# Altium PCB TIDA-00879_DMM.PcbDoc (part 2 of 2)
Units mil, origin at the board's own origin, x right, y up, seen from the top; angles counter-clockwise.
Board outline 2700 x 5000 mil, 4 copper layers (Layer 1 - Top Layer, Layer 2 - GND, Layer 3 - PWR, Layer 4 - Bottom Layer), stack 61.434 mil thick; 140 components, 132 nets, 483 pads, 130 vias.
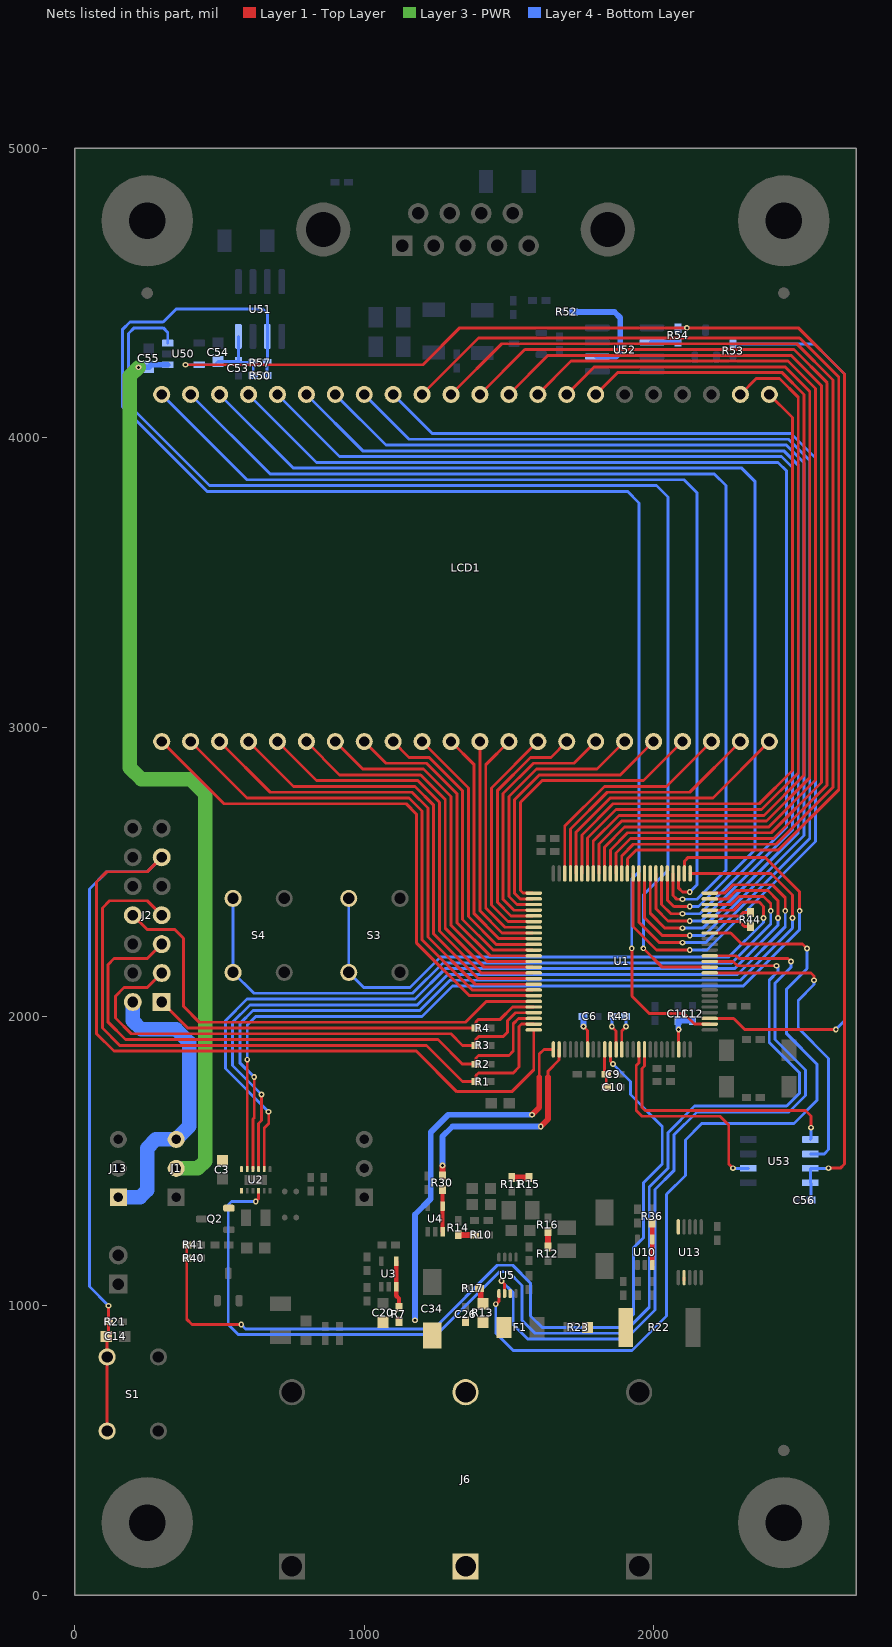
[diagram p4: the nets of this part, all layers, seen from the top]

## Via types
v1: diameter 20, hole 10, Layer 1 - Top Layer to Layer 4 - Bottom Layer, tented both sides, 127 vias
v2: diameter 19.68, hole 7.87, Layer 1 - Top Layer to Layer 4 - Bottom Layer, 3 vias

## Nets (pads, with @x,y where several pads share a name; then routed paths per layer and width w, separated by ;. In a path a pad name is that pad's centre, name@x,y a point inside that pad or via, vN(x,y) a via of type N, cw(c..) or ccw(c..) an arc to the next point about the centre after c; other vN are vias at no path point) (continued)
NetR7_2: R7.2 U3.3 U3.4 | length 164.6
  Layer 1 - Top Layer w15: U3.4@1110.59,1154.29 U3.3@1110.59,1065.71 1110.59,1034.41 1120,1025 R7.2@1120,993.62
NetR10_1: R10.1 R14.2 | length 56.9
  Layer 1 - Top Layer w20: R14.2@1325,1246.38 1326.38,1245 R10.1@1381.38,1245
NetR11_1: R11.1 R15.2 | length 60
  Layer 1 - Top Layer w20: R11.1@1510,1443.62 R15.2@1570,1443.62
NetR12_1: R12.1 R16.2 | length 52.8
  Layer 1 - Top Layer w20: R12.1@1635,1203.62 R16.2@1635,1256.38
NetR13_1: R13.1 R17.2 | length 58.2
  Layer 1 - Top Layer w20: R17.2@1398.62,1060 1403,1055.62 1403,1013.5 R13.1@1410,1006.5
NetR22_2: R22.2 R23.1 U13.5 U13.7 | length 10
  Layer 1 - Top Layer w10: U13.7@2105.32,1087.4 U13.7@2105.32,1097.4
NetR30_2: R30.2 U4.3 U4.4 | length 145.9
  Layer 1 - Top Layer w15: R30.2@1270,1401.38 1270.59,1400.79 U4.4@1270.59,1344.29 U4.3@1270.59,1255.71
NetR36_2: R36.2 U10.3 U10.4 | length 145.9
  Layer 1 - Top Layer w15: R36.2@1995,1286.38 1995.59,1285.79 U10.4@1995.59,1229.29 U10.3@1995.59,1140.71
NetR40_2: R40.2 R41.1 U1.11 | length 3105.5
  Layer 1 - Top Layer w10: R41.1@386.38,1210 R40.2@386.38,1165 386.38,953.62 405,935 v1@570,935 ; U1.11@1850.63,1885.87 1850.63,1844.37 v1(1859.53,1835.47)
  Layer 4 - Bottom Layer w10: v1(575,935) 590,920 1240,920 1460,1140 1513,1140 1575,1078 1575,965 1615,925 1885,925 1930,970 1930,1200 1965,1235 1965,1425 2030,1490 2030,1620 1920,1730 1920,1775 v1(1859.53,1835.47)
NetR43_1: R43.1 U1.13 | length 120.2
  Layer 1 - Top Layer w10: U1.13@1890,1885.87 1890,1950 v1@1905,1965
  Layer 4 - Bottom Layer w10: R43.1@1903.62,2000 1904.53,1999.09 v1(1904.53,1965.47)
NetR43_2: R43.2 U1.12 | length 120.1
  Layer 1 - Top Layer w10: v1@1855.31,1965 1870.31,1950 U1.12@1870.31,1885.87
  Layer 4 - Bottom Layer w10: v1(1855.79,1965.47) 1855.79,1999.41 R43.2@1856.38,2000
NetR44_1: R44.1 U1.46 | length 145.5
  Layer 1 - Top Layer w10: U1.46@2194.13,2347.48 2297.48,2347.48 2308.62,2358.62 R44.1@2335,2358.62
NetR44_2: R44.2 U1.45 | length 147.7
  Layer 1 - Top Layer w10: U1.45@2194.13,2327.8 2297.2,2327.8 2313.62,2311.38 R44.2@2335,2311.38
NetR52_1: R52.1 U52.6 | length 380.4
  Layer 4 - Bottom Layer w20: R52.1@1718.62,4435 R52.1@1723.62,4435 1865,4435 1885,4415 1885,4295 1870,4280 U52.6@1805.51,4280
NetR54_2: R54.2 U52.2 | length 91.1
  Layer 4 - Bottom Layer w20: U52.2@1994.49,4330 2083.62,4330 R54.2@2085,4331.38
NetS3_3: S3.3 S3.4 U1.47 | length 2062.9
  Layer 1 - Top Layer w10: U1.47@2194.13,2367.17 2277.17,2367.17 2305,2395 2365,2395 2380,2380 v1(2380,2340)
  Layer 4 - Bottom Layer w10: S3.3@946.42,2407.95 S3.4@946.42,2152.05 998.46,2100 1158.58,2100 1263.58,2205 2260,2205 2380,2325 v1(2380,2340)
NetS4_3: S4.3 S4.4 U1.48 | length 2546.6
  Layer 1 - Top Layer w10: U1.48@2194.13,2386.85 2266.85,2386.85 2295,2415 2380,2415 2405,2390 v1(2405,2365)
  Layer 4 - Bottom Layer w10: S4.3@546.42,2407.95 S4.4@546.42,2152.05 618.46,2080 1166.86,2080 1271.86,2185 2270,2185 2405,2320 v1(2405,2365)
NetU1_38: U1.38 U2.4 | length 4187.1
  Layer 1 - Top Layer w10: v1(625,1360) 634.84,1369.84 U2.4@634.84,1397.6 ; U1.38@2194.13,2190 2275,2190 2290,2175 v1(2425,2175)
  Layer 4 - Bottom Layer w10: v1(625,1360) 541.44,1360 530,1348.56 530,935 565,900 1250,900 1467.5,1117.5 1497.5,1117.5 1545,1070 1545,950 1590,905 1895,905 1985,995 1985,1410 2050,1475 2050,1598.28 2141.72,1690 2460,1690 2505,1735 2505,1805 2400,1910 2400,2125 2430,2155 2430,2170 v1(2425,2175)
NetU1_49: U1.49 U2.8 | length 2975.5
  Layer 1 - Top Layer w10: U2.8@654.53,1472.4 654.53,1614.53 670,1630 v1@670,1670.47 ; U1.49@2194.13,2406.54 2256.54,2406.54 2285,2435 2395,2435 2430,2400 v1(2430,2340)
  Layer 4 - Bottom Layer w10: v1@670,1670 v1(669.53,1670.47) 520,1820 520,1985 595,2060 1175.15,2060 1280.15,2165 2280,2165 2430,2315 v1(2430,2340)
NetU1_50: U1.50 U2.9 | length 2991.3
  Layer 1 - Top Layer w10: U2.9@634.84,1472.4 634.84,1629.84 645,1640 v1@645,1730 ; U1.50@2194.13,2426.22 2246.22,2426.22 2275,2455 2410,2455 2455,2410 v1(2455,2365)
  Layer 4 - Bottom Layer w10: v1@645,1730 v1(644.53,1730.47) 545,1830 545,1980 605,2040 1183.43,2040 1288.43,2145 2290,2145 2455,2310 v1(2455,2365)
NetU1_51: U1.51 U2.10 | length 3072
  Layer 1 - Top Layer w10: U2.10@615.16,1472.4 615.16,1645.16 620,1650 v1@620,1790.47 ; U1.51@2126.22,2494.13 2405.87,2494.13 2480,2420 v1(2480,2340)
  Layer 4 - Bottom Layer w10: v1@620,1790 v1(619.53,1790.47) 570,1840 570,1975 615,2020 1191.72,2020 1296.72,2125 2300,2125 2480,2305 v1(2480,2340)
NetU1_52: U1.52 U2.11 | length 3170.2
  Layer 1 - Top Layer w10: U2.11@595.47,1472.4 v1(595.47,1850.47) ; U1.52@2106.54,2494.13 2106.54,2536.54 2120,2550 2385,2550 2505,2430 v1(2505,2365)
  Layer 4 - Bottom Layer w10: v1(595.47,1850.47) 595.47,1970.47 625,2000 1200,2000 1305,2105 2310,2105 2505,2300 v1(2505,2365)
RESET: C14.1 J2.11 R21.1 S1.1 S1.2 U1.100 | length 4748.4
  Layer 1 - Top Layer w10: S1.2@111.42,567.04 S1.1@111.42,822.95 111.42,891.72 C14.1@108.96,894.19 116.38,901.61 R21.1@116.38,945 v1(116.38,1000) ; J2.11@300,2550 250,2500 110,2500 75,2465 75,1940 135,1880 1180,1880 1320,1740 1510,1740 1585.87,1815.87 U1.100@1585.87,1953.78
  Layer 4 - Bottom Layer w10: v1(116.38,1000) 50,1066.38 50,2440 110,2500 250,2500 J2.11@300,2550
RXD: R50.2 R57.1 U1.27 U51.6 | length 4965.7
  Layer 1 - Top Layer w10: v1@1925,2235 1925,2070 1985,2010 2105,2010 2141.54,1973.46 U1.27@2194.13,1973.46
  Layer 4 - Bottom Layer w10: R50.2@663.62,4215 R57.1@663.62,4260 665,4261.38 U51.6@665,4350.51 665,4430 650,4445 350,4445 305,4400 190,4400 165,4375 165,4106.72 456.72,3815 1910,3815 1950,3775 1950,2500 1924.53,2474.53 v1(1924.53,2235.47)
S0: LCD1.1 U1.94 | length 1905.3
  Layer 1 - Top Layer w10: LCD1.1@300,2950 515,2735 1145,2735 1180,2700 1180,2255 1363.11,2071.89 U1.94@1580.87,2071.89
S1: LCD1.2 U1.93 | length 1797.1
  Layer 1 - Top Layer w10: LCD1.2@400,2950 595,2755 1155,2755 1200,2710 1200,2265 1373.43,2091.57 U1.93@1580.87,2091.57
S2: LCD1.3 U1.92 | length 1689
  Layer 1 - Top Layer w10: LCD1.3@500,2950 675,2775 1165,2775 1220,2720 1220,2275 1383.74,2111.26 U1.92@1580.87,2111.26
S3: LCD1.4 U1.91 | length 1580.8
  Layer 1 - Top Layer w10: LCD1.4@600,2950 755,2795 1175,2795 1240,2730 1240,2285 1394.06,2130.94 U1.91@1580.87,2130.94
S4: LCD1.5 U1.90 | length 1472.7
  Layer 1 - Top Layer w10: LCD1.5@700,2950 835,2815 1185,2815 1260,2740 1260,2295 1404.37,2150.63 U1.90@1580.87,2150.63
S5: LCD1.6 U1.89 | length 1364.5
  Layer 1 - Top Layer w10: LCD1.6@800,2950 915,2835 1195,2835 1280,2750 1280,2305 1414.69,2170.31 U1.89@1580.87,2170.31
S6: LCD1.7 U1.88 | length 1256.3
  Layer 1 - Top Layer w10: LCD1.7@900,2950 995,2855 1205,2855 1300,2760 1300,2315 1425,2190 U1.88@1580.87,2190
S7: LCD1.8 U1.87 | length 1148.2
  Layer 1 - Top Layer w10: LCD1.8@1000,2950 1075,2875 1215,2875 1320,2770 1320,2325 1435.32,2209.68 U1.87@1580.87,2209.68
S8: LCD1.9 U1.86 | length 1040
  Layer 1 - Top Layer w10: LCD1.9@1100,2950 1155,2895 1225,2895 1340,2780 1340,2335 1445.63,2229.37 U1.86@1580.87,2229.37
S9: LCD1.10 U1.85 | length 931.9
  Layer 1 - Top Layer w10: LCD1.10@1200,2950 1360,2790 1360,2345 1455.94,2249.06 U1.85@1580.87,2249.06
S10: LCD1.11 U1.84 | length 864.7
  Layer 1 - Top Layer w10: LCD1.11@1300,2950 1380,2870 1380,2355 1466.26,2268.74 U1.84@1580.87,2268.74
S11: LCD1.12 U1.83 | length 797.6
  Layer 1 - Top Layer w10: LCD1.12@1400,2950 1400,2365 1476.57,2288.43 U1.83@1580.87,2288.43
S12: LCD1.13 U1.82 | length 796.7
  Layer 1 - Top Layer w10: LCD1.13@1500,2950 1420,2870 1420,2375 1486.89,2308.11 U1.82@1580.87,2308.11
S13: LCD1.14 U1.81 | length 795.8
  Layer 1 - Top Layer w10: U1.81@1580.87,2327.8 1497.2,2327.8 1440,2385 1440,2790 LCD1.14@1600,2950
S14: LCD1.15 U1.80 | length 836
  Layer 1 - Top Layer w10: U1.80@1580.87,2347.48 1507.52,2347.48 1460,2395 1460,2780 1575,2895 1645,2895 LCD1.15@1700,2950
S15: LCD1.16 U1.79 | length 876.1
  Layer 1 - Top Layer w10: U1.79@1580.87,2367.17 1517.83,2367.17 1480,2405 1480,2770 1585,2875 1725,2875 LCD1.16@1800,2950
S16: LCD1.17 U1.78 | length 916.2
  Layer 1 - Top Layer w10: U1.78@1580.87,2386.85 1528.15,2386.85 1500,2415 1500,2760 1595,2855 1805,2855 LCD1.17@1900,2950
S17: LCD1.18 U1.77 | length 956.4
  Layer 1 - Top Layer w10: U1.77@1580.87,2406.54 1538.46,2406.54 1520,2425 1520,2750 1605,2835 1885,2835 LCD1.18@2000,2950
S18: LCD1.19 U1.76 | length 996.5
  Layer 1 - Top Layer w10: U1.76@1580.87,2426.22 1548.78,2426.22 1540,2435 1540,2740 1615,2815 1965,2815 LCD1.19@2100,2950
S19: LCD1.20 U1.73 | length 791.8
  Layer 1 - Top Layer w10: U1.73@1693.15,2494.13 1693.15,2658.15 1830,2795 2045,2795 LCD1.20@2200,2950
S20: LCD1.21 U1.72 | length 866
  Layer 1 - Top Layer w10: U1.72@1712.83,2494.13 1712.83,2647.83 1840,2775 2125,2775 LCD1.21@2300,2950
S21: LCD1.22 U1.71 | length 940.3
  Layer 1 - Top Layer w10: U1.71@1732.52,2494.13 1732.52,2637.52 1850,2755 2205,2755 LCD1.22@2400,2950
S22: LCD1.23 U1.70 | length 2286.3
  Layer 1 - Top Layer w10: U1.70@1752.2,2494.13 1752.2,2627.2 1860,2735 2365,2735 2480,2850 2480,4070 LCD1.23@2400,4150
S23: LCD1.24 U1.69 | length 2492
  Layer 1 - Top Layer w10: U1.69@1771.89,2494.13 1771.89,2616.89 1870,2715 2373.28,2715 2500,2841.72 2500,4140 2435,4205 2355,4205 LCD1.24@2300,4150
S24: LCD1.29 U1.68 | length 3033.5
  Layer 1 - Top Layer w10: U1.68@1791.57,2494.13 1791.57,2606.57 1880,2695 2381.57,2695 2520,2833.43 2520,4150 2445,4225 1875,4225 LCD1.29@1800,4150
S25: LCD1.30 U1.67 | length 3175.1
  Layer 1 - Top Layer w10: LCD1.30@1700,4150 1795,4245 2455,4245 2540,4160 2540,2825.15 2389.85,2675 1890,2675 1811.26,2596.26 U1.67@1811.26,2494.13
S26: LCD1.31 U1.66 | length 3316.6
  Layer 1 - Top Layer w10: LCD1.31@1600,4150 1715,4265 2465,4265 2560,4170 2560,2816.86 2398.14,2655 1900,2655 1830.94,2585.94 U1.66@1830.94,2494.13
S27: LCD1.32 U1.65 | length 3458.2
  Layer 1 - Top Layer w10: LCD1.32@1500,4150 1635,4285 2475,4285 2580,4180 2580,2808.58 2406.42,2635 1910,2635 1850.63,2575.63 U1.65@1850.63,2494.13
S28: LCD1.33 U1.64 | length 3599.7
  Layer 1 - Top Layer w10: LCD1.33@1400,4150 1555,4305 2485,4305 2600,4190 2600,2800.29 2414.71,2615 1920,2615 1870.31,2565.31 U1.64@1870.31,2494.13
S29: LCD1.34 U1.63 | length 3741.3
  Layer 1 - Top Layer w10: LCD1.34@1300,4150 1475,4325 2495,4325 2620,4200 2620,2792.01 2422.99,2595 1930,2595 1890,2555 U1.63@1890,2494.13
S30: LCD1.35 U1.62 | length 3882.8
  Layer 1 - Top Layer w10: LCD1.35@1200,4150 1395,4345 2505,4345 2640,4210 2640,2783.73 2431.27,2575 1940,2575 1909.68,2544.68 U1.62@1909.68,2494.13
S31: LCD1.36 U1.61 | length 3879
  Layer 1 - Top Layer w10: U1.61@1929.37,2494.13 1929.37,2310.63 2010,2230 v1(2125,2230)
  Layer 4 - Bottom Layer w10: LCD1.36@1100,4150 1235,4015 2475,4015 2560,3930 2560,2605 2185,2230 v1(2125,2230)
S32: LCD1.37 U1.60 | length 3878.9
  Layer 1 - Top Layer w10: U1.60@1949.06,2494.13 1949.06,2325.94 2020,2255 v1(2100,2255)
  Layer 4 - Bottom Layer w10: LCD1.37@1000,4150 1155,3995 2466.72,3995 2540,3921.72 2540,2615 2180,2255 v1(2100,2255)
S33: LCD1.38 U1.59 | length 3878.8
  Layer 1 - Top Layer w10: U1.59@1968.74,2494.13 1968.74,2341.26 2030,2280 v1(2125,2280)
  Layer 4 - Bottom Layer w10: LCD1.38@900,4150 1075,3975 2458.43,3975 2520,3913.43 2520,2625 2175,2280 v1(2125,2280)
S34: LCD1.39 U1.58 | length 3878.8
  Layer 1 - Top Layer w10: U1.58@1988.43,2494.13 1988.43,2356.57 2040,2305 v1(2100,2305)
  Layer 4 - Bottom Layer w10: LCD1.39@800,4150 995,3955 2450.15,3955 2500,3905.15 2500,2635 2170,2305 v1(2100,2305)
S35: LCD1.40 U1.57 | length 3878.7
  Layer 1 - Top Layer w10: U1.57@2008.11,2494.13 2008.11,2371.89 2050,2330 v1(2125,2330)
  Layer 4 - Bottom Layer w10: LCD1.40@700,4150 915,3935 2441.86,3935 2480,3896.86 2480,2645 2165,2330 v1(2125,2330)
S36: LCD1.41 U1.56 | length 3876.5
  Layer 1 - Top Layer w10: U1.56@2027.8,2494.13 2027.8,2387.2 2060,2355 v1(2100,2355)
  Layer 4 - Bottom Layer w10: LCD1.41@600,4150 835,3915 2430,3915 2460,3885 2460,2655 2160,2355 v1(2100,2355)
S37: LCD1.42 U1.55 | length 3733.5
  Layer 1 - Top Layer w10: U1.55@2047.48,2494.13 2047.48,2402.52 2070,2380 v1(2125,2380)
  Layer 4 - Bottom Layer w10: LCD1.42@500,4150 755,3895 2305,3895 2350,3850 2350,2575 2155,2380 v1(2125,2380)
S38: LCD1.43 U1.54 | length 3616.3
  Layer 1 - Top Layer w10: U1.54@2067.17,2494.13 2067.17,2417.83 2080,2405 v1(2100,2405)
  Layer 4 - Bottom Layer w10: LCD1.43@400,4150 675,3875 2210,3875 2250,3835 2250,2505 2150,2405 v1(2100,2405)
S39: LCD1.44 U1.53 | length 3475.8
  Layer 1 - Top Layer w10: U1.53@2086.85,2494.13 2086.85,2443.15 2100,2430 v1(2125,2430)
  Layer 4 - Bottom Layer w10: LCD1.44@300,4150 595,3855 2105,3855 2150,3810 2150,2455 v1(2125,2430)
SCLK: U1.36 U53.6 | length 1100.5
  Layer 1 - Top Layer w10: U1.36@2194.13,2150.63 2544.37,2150.63 2555,2140 v1(2555,2125)
  Layer 4 - Bottom Layer w10: U53.6@2542.28,1525 2590,1525 2605,1540 2605,1855 2500,1960 2500,2055 2555,2110 v1(2555,2125)
SIMO: U1.17 U53.5 | length 882.6
  Layer 1 - Top Layer w10: U1.17@1968.74,1885.87 1968.74,1828.74 1960,1820 1960,1685 1970,1675 2525,1675 2544.53,1655.47 v1(2544.53,1615.47)
  Layer 4 - Bottom Layer w10: U53.5@2542.28,1575 2544.53,1577.24 v1(2544.53,1615.47)
SOMI: U1.16 U53.2 | length 764.9
  Layer 1 - Top Layer w10: U1.16@1949.06,1885.87 1949.06,1839.06 1940,1830 1940,1675 1960,1655 2230,1655 2260,1625 2260,1490 v1(2274.53,1475.47) v1@2275,1475
  Layer 4 - Bottom Layer w10: v1(2274.53,1475.47) 2275,1475 U53.2@2327.72,1475
TCK: J2.7 R1.1 U1.99 | length 2395.3
  Layer 1 - Top Layer w10: J2.7@300,2350 250,2400 120,2400 95,2375 95,1960 155,1900 1215,1900 1340,1775 R1.1@1386.38,1775 1386.38,1796.38 1395,1805 1515,1805 1535,1825 1535,1965 1543.46,1973.46 U1.99@1585.87,1973.46
TDI: J2.3 R3.1 U1.97 | length 1836
  Layer 1 - Top Layer w10: J2.3@300,2150 250,2100 170,2100 140,2070 140,1995 195,1940 1300,1940 1340,1900 R3.1@1386.38,1900 1386.38,1921.38 1395,1930 1480,1930 1495,1945 1495,1985 1522.83,2012.83 U1.97@1585.87,2012.83
TDO: J2.1 R4.1 U1.96 | length 1365.7
  Layer 1 - Top Layer w10: J2.1@300,2050 390,1960 R4.1@1386.38,1960 1386.38,1981.38 1395,1990 1470,1990 1512.52,2032.52 U1.96@1585.87,2032.52
TEST/SBWTCK: J2.8 U1.95 | length 1706.7
  Layer 1 - Top Layer w10: J2.8@200,2350 250,2300 345,2300 375,2270 375,2035 430,1980 1350,1980 1422.2,2052.2 U1.95@1585.87,2052.2
TEST_EN: U1.37 U50.3 | length 4280.9
  Layer 1 - Top Layer w10: v1@1965,2235 2029.69,2170.31 U1.37@2194.13,2170.31
  Layer 4 - Bottom Layer w10: U50.3@320.87,4327.4 320.87,4364.13 305,4380 205,4380 185,4360 185,4115 465,3835 2010,3835 2050,3795 2050,2505 1964.53,2419.53 v1(1964.53,2235.47)
TMS: J2.5 R2.1 U1.98 | length 2078.6
  Layer 1 - Top Layer w10: J2.5@300,2250 250,2200 135,2200 115,2180 115,1980 175,1920 1255,1920 1340,1835 R2.1@1386.38,1835 1386.38,1856.38 1395,1865 1500,1865 1515,1880 1515,1975 1533.15,1993.15 U1.98@1585.87,1993.15
TXD: R53.1 U1.28 | length 3157
  Layer 1 - Top Layer w10: U1.28@2194.13,1993.15 2276.85,1993.15 2315,1955 v1(2630,1955)
  Layer 4 - Bottom Layer w10: R53.1@2275,4323.62 2556.38,4323.62 2660,4220 2660,1985 v1(2630,1955)
V+: C20.1 C26.2 C34.2 F1.1 J6.1 J6.2 R7.1 R13.2 U1.1 U5.7 | length 1323.3
  Layer 1 - Top Layer w10: 1605,1790 1605,1870 1620.87,1885.87 U1.1@1653.78,1885.87
  Layer 1 - Top Layer w20: v1(1580,1660) 1605,1685 1605,1790
  Layer 4 - Bottom Layer w20: v1(1175,950) 1175,1315 1230,1370 1230,1600 1290,1660 v1(1580,1660)
V-: R30.1 U1.2 | length 783
  Layer 1 - Top Layer w10: 1635,1790 1635,1810.56 1673.46,1849.02 U1.2@1673.46,1885.87
  Layer 1 - Top Layer w20: R30.1@1270,1448.62 v1(1270,1485) ; v1(1610,1620) 1635,1645 1635,1790
  Layer 4 - Bottom Layer w20: v1(1270,1485) 1270,1585 1305,1620 v1(1610,1620)
VASYS: C9.1 C10.2 U1.10 | length 133.1
  Layer 1 - Top Layer w10: U1.10@1830.94,1885.87 1830.94,1805.43 C9.1@1836.38,1800 C10.2@1836.38,1755
VCORE: C11.1 C12.1 U1.23 | length 151.3
  Layer 1 - Top Layer w10: U1.23@2086.85,1885.87 v1(2086.85,1955)
  Layer 4 - Bottom Layer w20: v1(2086.85,1955) 2085,1956.85 C11.1@2085,1986.38 C12.1@2135,1986.38
VIN: C3.1 C55.1 J1.2 Q2.2 U2.1 U2.12 U50.1 | length 3178.2
  Layer 3 - PWR w50: v1(220,4243.5) 190,4213.5 190,2860 230,2820 400,2820 450,2770 450,1500 425,1475 J1.2@350,1475
  Layer 4 - Bottom Layer w20: v1(220,4243.5) C55.1@255,4243.5 264.09,4252.6 U50.1@320.87,4252.6
VJTAG: J1.3 J2.2 J13.1 | length 1012.5
  Layer 4 - Bottom Layer w50: J13.1@150,1375 225.01,1375 250,1400 250,1545 280.01,1575 J1.3@350,1575 395,1620 395,1910 350,1955 230,1955 200,1985 J2.2@200,2050
VRANGE_0: U1.39 U5.6 | length 2728.7
  Layer 1 - Top Layer w10: v1@1475,1085 1485.16,1074.84 U5.6@1485.16,1042.01 ; U1.39@2194.13,2209.68 2285.32,2209.68 2295,2200 2465,2200 v1(2475,2190)
  Layer 4 - Bottom Layer w10: v1(1474.53,1085.47) 1515,1045 1515,935 1565,885 1905,885 2005,985 2005,1401.72 2070,1466.72 2070,1590 2150,1670 2468.28,1670 2525,1726.72 2525,1815 2420,1920 2420,2115 2475,2170 v1(2475,2190)
VRANGE_1: U1.43 U5.5 | length 2908.9
  Layer 1 - Top Layer w10: v1@1455,1005 1465.47,1015.47 U5.5@1465.47,1042.01 ; U1.43@2194.13,2288.43 2266.57,2288.43 2305,2250 2515,2250 v1(2530,2235)
  Layer 4 - Bottom Layer w10: v1(1454.53,1005.47) 1454.53,905.47 1515,845 1925,845 2045,965 2045,1385.15 2110,1450.15 2110,1573.43 2166.57,1630 2484.85,1630 2565,1710.15 2565,1835 2460,1940 2460,2095 2530,2165 v1(2530,2235)
VREF: C6.1 U1.7 | length 119.9
  Layer 1 - Top Layer w10: v1@1758.46,1965 1771.89,1951.57 U1.7@1771.89,1885.87
  Layer 4 - Bottom Layer w20: C6.1@1756.38,2000 1757.99,1998.39 v1(1757.99,1965.47)
VTEST: C53.1 C54.1 C56.1 R50.1 R54.1 R57.2 U50.5 U51.8 U53.7 U53.8 | length 5763.5
  Layer 1 - Top Layer w10: v1(382.6,4252.6) 1202.6,4252.6 1330,4380 v1(2115,4380) 2500,4380 2660,4220 2660,1490 2645.47,1475.47 v1(2604.53,1475.47)
  Layer 4 - Bottom Layer w10: v1(382.6,4252.6) U50.5@429.13,4252.6 484.09,4252.6 C54.1@495,4263.5 495.12,4263.62 C53.1@565,4263.62 ; U51.8@565,4350.51 C53.1@565,4263.62 ; R50.1@616.38,4215 R57.2@616.38,4260 568.62,4260 C53.1@565,4263.62 ; R54.1@2085,4378.62 2086.38,4380 v1(2115,4380) ; C56.1@2543.62,1365 2543.62,1423.66 U53.8@2542.28,1425 U53.7@2542.28,1475 v1@2605,1475
pads on no net: FID1.1 FID2.1 FID3.1 FID4.1 FID5.1 FID6.1 H3.1 H4.1 H8.1 H9.1 J2.6 J2.10 J2.12 J2.13 J2.14 J11.1 J11.6 J11.8 J11.9 U1.15 U1.30 U1.31 U1.40 U1.41 U2.7 U13.10 U51.1 U51.4 U51.7 U52.1 U52.4 U52.7 U53.3
copper on no net: | length 35.2
  Layer 1 - Top Layer w20: 1362.24,1117.6 v1(1397.4,1117.6)

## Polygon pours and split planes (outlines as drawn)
DGND on Layer 2 - GND "Layer 2 - GND - DGND" (solid, remove dead copper, pour order 8): 20,20 2680,20 2680,4980 20,4980
AGND on Layer 2 - GND "Layer 2 - GND - AGND" (solid, remove dead copper, pour order 6): 840,900 840,1400 770,1400 770,1650 1520,1650 1520,2010 1950,2010 1950,1370 2340,1370 2340,900
DGND on Layer 3 - PWR "Layer 3 - PWR - DGND" (solid, remove dead copper, pour order 7): 20,20 2680,20 2680,4980 20,4980
AGND on Layer 3 - PWR "Layer 3 - PWR - AGND" (solid, remove dead copper, pour order 5): 840,900 840,1400 770,1400 770,1650 1520,1650 1520,2010 1950,2010 1950,1370 2340,1370 2340,900

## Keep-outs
Keep-Out Layer:
  text ".Layer_Name" at 577,-858.49 h60

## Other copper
Layer 1 - Top Layer:
  rectangle net NetC27_1: 674,845 822,900
  region net AGND: 1758,1915 1758,1818 1753,1813 1753,1735 1743,1725 1729,1725 1719,1735 1719,1814 1726,1821 1726,1915
  region net DVCC: 1818,1915 1818,1831 1800,1813 1800,1735 1790,1725 1775,1725 1765,1735 1765,1810 1805,1850 1805,1915
  region net DVCC: 2041,1915 2041,1735 2051,1725 2085,1725 2095,1735 2095,1822 2080,1837 2066,1837 2054,1849 2054,1915
  region net DGND: 1660,2465 1620,2465 1585,2500 1585,2675 1595,2685 1618,2685 1628,2675 1628,2552 1660,2520
  region net DVSYS: 1680,2465 1680,2675 1670,2685 1650,2685 1640,2675 1640,2560 1667,2533 1667,2465
  region net DGND: 490,1420 490,1460 495,1465 535,1465 547,1453 685,1453 685,1417 493,1417
  region net VIN: 390,1515 415,1540 563,1540 581,1522 581,1462 561,1462 543,1480 485,1480 470,1465 470,1415 485,1400 553,1400 561,1408 581,1408 581,1356 550,1325 470,1325 410,1385 410,1415 390,1435 325,1435 310,1450 310,1500 325,1515
  region net DGND: 1982,1915 2014,1915 2014,1846 2030,1830 2030,1735 2020,1725 1990,1725 1980,1735 1980,1820 1982,1822
  region net DGND: 2350,1705 2485,1705 2500,1720 2500,1920 2485,1935 2350,1935
  region net NetC27_1: 880,45 945,110 945,900 690,900 690,45
  region net V+: 1105,45 1040,110 1040,965 1450,965 1499,1014 1499,1058 1511,1058 1511,111 1445,45
  region net NetJ9_1: 2100,45 2165,110 2165,1037 2151,1051 2151,1300 2138,1300 2138,1051 2100,1013 2100,935 1895,730 1895,45
  region net I+: 1565,880 1720,880 1730,890 1730,960 1720,970 1565,970
  region net NetR22_2: 1750,975 1770,995 2005,995 2030,1020 2063.5,1053.5 2088.5,1053.5 2099,1064 2099,1170 2079.5,1189.5 2079.5,1300 2092,1300 2092,1195 2112,1175 2112,1061 2112,1047 2085,1020 2085,945 1995,855 1770,855 1750,875
  region net NetC27_1: 674,845 674,838 692,820 703,831 708,831 708,851 700,859 686,845
  text ".Layer_Name" at 577,-858.49 h60
Layer 2 - GND:
  pour cut-out: 1510,1680 1440,1680 1440,2040 1510,2040
  pour cut-out: 150,2000 150,2700 350,2700 350,2490 260,2490 260,2410 350,2410 350,2000
  pour cut-out: 1095,1040 1125,1040 1125,1180 1095,1180
  pour cut-out: 1255,1230 1285,1230 1285,1370 1255,1370
  pour cut-out: 1979.99,1114.41 2009.99,1114.41 2009.99,1254.41 1979.99,1254.41
Layer 3 - PWR:
  pour cut-out: 1095,1040 1125,1040 1125,1180 1095,1180
  pour cut-out: 1255,1230 1285,1230 1285,1370 1255,1370
  pour cut-out: 1979.99,1114.41 2009.99,1114.41 2009.99,1254.41 1979.99,1254.41
  pour cut-out: 150,2000 150,2700 350,2700 350,2490 260,2490 260,2410 350,2410 350,2000
Layer 4 - Bottom Layer:
  text ".Layer_Name" at 577,-858.49 h60

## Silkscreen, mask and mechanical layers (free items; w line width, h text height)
Top Overlay:
  lines w7: 420,1640 420,1535 670,1535 670,1640 ; 558.07,840 2410,840 2410,1640 ; 642,837 643,838 643,1066 713,1066 919,1066 920,1067 920,1640 ; 642,980 616.13,980 558.07,980 60,980 60,1640 920,1640 ; 1345,1640 1345,2655 2595,2655 2595,1640 2410,1640 ; 1845,1640 1845,1535 2095,1535 2095,1640 ; 1845,2655 1845,2550 2095,2550 2095,2655 ; 920,1640 2410,1640
  text "MCU" at 1875,2570 h100
  text "Range" at 495,2029 h60
  text "Mode" at 929,2019 h60
  text "3" at 1074,1564 h40
  text "3" at 230,1560 h40
  text "PWR" at 445,1555 h100
  text "AFE" at 1880,1555 h100
  text "2" at 1072,1457 h40
  text "2" at 228,1453 h40
  text "1" at 1081,1348 h40
  text "1" at 237,1344 h40
  text "+" at 220,1158 h60
  text "-" at 217,1019 h60
  text "RESET" at 65,452 h100
  text "WARNING / HIGH / VOLTAGE" at 2249,371 h75
  text ".Layer_Name" at 577,-858.49 h60
Bottom Overlay:
  text ".Layer_Name" at 577,-858.49 h60
Top Paste:
  text ".Layer_Name" at 577,-858.49 h60
Bottom Paste:
  text ".Layer_Name" at 577,-858.49 h60
Top Solder:
  text ".Layer_Name" at 577,-858.49 h60
  text ".Layer_Name" at 577,-858.49 h60
Bottom Solder:
  text ".Layer_Name" at 577,-858.49 h60
Drill Guide:
  text ".Layer_Name" at 577,-858.49 h60
M1 Board Outline:
  the board outline again, w10
  text ".Layer_Name" at 577,-858.49 h60
M2 Board Dimensions:
  rectangle: 0,-275 125,-150
  rectangle: 125,-400 500,-275
  lines w7: 0,-275 1000,-275 ; 125,-400 125,-150 ; 250,-400 250,-150 ; 500,-400 500,-150 ; 750,-400 750,-150 ; 0,-400 1000,-400 1000,-150 0,-150 0,-400
  text ".Layer_Name" at 577,-858.49 h60
M3 3D STEP Top:
  text ".Layer_Name" at 577,-858.49 h60
M4 3D STEP Bottom:
  text ".Layer_Name" at 577,-858.49 h60
M5 Assembly Top:
  lines w10: -292,-930.17 6308,-930.17 ; -292,-726.83 6310,-726.83 ; -292,-523.5 -292,-1133.5 3713,-1133.5 6310,-1133.5 6310,-523.5 -291.5,-523.5 -291.5,-1133.5 1284,-1133.5 ; 2173,-1133.5 2173,-523.5 ; 3440,-726.83 3440,-523.5 ; 4280,-726.83 4280,-523.5 ; 4902,-1140 4902,-937.17
  text "COMPONENTS MARKED 'DNP' SHOULD NOT BE POPULATED." at 1153.5,-318.5 h60
  text "ASSEMBLY VARIANT:" at 1153,-434 h60
  text ".VariantName" at 2189,-434 h60
  text "PCB VIEWED FROM TOP SIDE" at -228.5,-655.67 h60
  text "BOARD #:" at 2248,-655.67 h60
  text ".PRJ_Number" at 2793.5,-655.67 h60
  text "REV:" at 3638,-655.67 h60
  text ".PCB_Rev" at 3929.5,-655.67 h60
  text "SVN REV:" at 4476,-655.67 h60
  text ".VersionControl_RevNumber" at 4982,-655.67 h60
  text "TID #:" at 2248,-859 h60
  text ".TID" at 2793.5,-859 h60
  text "PLOT NAME =" at -228.5,-1064.34 h60
  text ".plot_File_Name" at 577,-1064.34 h60
  text "GENERATED    :" at 2250,-1064.34 h60
  text ".Print_Date" at 3119.5,-1064.34 h60
  text ".Print_Time" at 3848.5,-1064.34 h60
  text "TEXAS INSTRUMENTS" at 5113,-1064.34 h60
M6 Assembly Bottom:
  lines w10: -292.5,-727.33 6309.5,-727.33 ; -290.5,-930.67 6309.5,-930.67 ; 1115.5,-1140.5 1115.5,-937.67 ; 1737.5,-727.33 1737.5,-524 ; 2577.5,-727.33 2577.5,-524 ; 3844.5,-1134 3844.5,-524 ; 4733.5,-1134 6309,-1134 6309,-524 -292.5,-524 -292.5,-1134 2304.5,-1134 6309.5,-1134 6309.5,-524
  text "COMPONENTS MARKED 'DNP' SHOULD NOT BE POPULATED." at 6102,-318 h60
  text ".VariantName" at 5058,-434 h60
  text "ASSEMBLY VARIANT:" at 6097,-434 h60
  text ".VersionControl_RevNumber" at 1035.5,-656.17 h60
  text "SVN REV:" at 1541.5,-656.17 h60
  text ".PCB_Rev" at 2088,-656.17 h60
  text "REV:" at 2379.5,-656.17 h60
  text ".PRJ_Number" at 3224,-656.17 h60
  text "BOARD #:" at 3769.5,-656.17 h60
  text "PCB VIEWED FROM BOTTOM SIDE" at 6246,-656.17 h60
  text ".TID" at 3224,-859.5 h60
  text "TID #:" at 3769.5,-859.5 h60
  text "TEXAS INSTRUMENTS" at 904.5,-1064.84 h60
  text ".Print_Time" at 2169,-1064.84 h60
  text ".Print_Date" at 2898,-1064.84 h60
  text "GENERATED    :" at 3767.5,-1064.84 h60
  text ".plot_File_Name" at 5440.5,-1064.84 h60
  text "PLOT NAME =" at 6246,-1064.84 h60
M9 Title Sheet:
  drawing of 1178 lines, arcs and shapes, not listed
  text "1" at 739.84,8036.5 h70
  text "2" at 3235.5,8036.5 h70
  text "3" at 5724.84,8036.5 h70
  text "4" at 8231.51,8036.5 h70
  text "5" at 10730.5,8036.5 h70
  text "6" at 13235.5,8036.5 h70
  text "A" at -416.5,6893.5 h70
  text "A" at 14383.5,6893.5 h70
  text "B" at -416.5,4513.5 h70
  text "B" at 14383.5,4513.5 h70
  text "C" at -416.5,2138.5 h70
  text "C" at 14383.5,2138.5 h70
  text "PROJECT TITLE:" at 11343.5,277.5 h45
  text ".PRJ_Title" at 11393.5,144.17 h70
  text "DESIGNED FOR:" at 11343.5,-23.5 h45
  text ".PRJ_Customer" at 11393.5,-163.5 h70
  text "D" at -416.5,-231.5 h70
  text "D" at 14383.5,-231.5 h70
  text "FILE NAME:" at 11343.5,-323.5 h45
  text ".PCB_File_Name_No_Path" at 11393.5,-443.5 h70
  text "Texas Instruments (TI) and/or its licensors do not warrant the accuracy or completeness of this specification" at 6374,-605.34 h45
  text "ENGINEER:" at 11343.5,-613.5 h45
  text "LAYOUT BY:" at 12848.5,-613.5 h45
  text "or any information contained therein. TI and/or its licensors do not warrant that this design will meet" at 6329.01,-718 h45
  text ".PRJ_Engineer" at 11393.5,-768.49 h70
  text ".PCB_Layout" at 12899,-768.49 h70
  text "JMM" at 12856.28,-803.5 h100
  text "s  o  l  u  t  i  o  n  s" at 13714.28,-806.5 h68
  text "the specifications, will be suitable for your application or fit for any particular purpose, or will operate in" at 6329.01,-830.67 h45
  text ".Layer_Name" at 577,-858.49 h60
  text "ALTIUM DESIGNER VERSION:" at 12848.5,-923.5 h45
  text "an implementation. TI and/or its licensors do not warrant that the design is production worthy. You should" at 6329.01,-943.33 h45
  text "completely validate and test your design implementation to confirm the system functionality for your application." at 6374,-1056 h45
  text ".print_Scale" at 11393.5,-1056.83 h70
  text ".Application_BuildNumber" at 12899,-1056.83 h70
  text "1" at 739.84,-1263.5 h70
  text "2" at 3235.5,-1263.5 h70
  text "3" at 5724.84,-1263.5 h70
  text "4" at 8231.51,-1263.5 h70
  text "5" at 10730.5,-1263.5 h70
  text "6" at 13235.5,-1263.5 h70
M10 Fab Notes:
  drawing of 173 lines, arcs and shapes, not listed
  text "DESIGN INFORMATION" at 12378.02,6201 h60
  text "MIN. TRACK WIDTH:" at 11733.46,6021 h60
  text "8" at 12829.7,6021 h60
  text "MIL" at 12984.46,6021 h60
  text "MIN. CLEARANCE:" at 11733.46,5889 h60
  text "0.2" at 12769.7,5889 h60
  text "mm" at 12984.46,5889 h60
  text "MIN. VIA PAD SIZE:" at 11733.46,5757 h60
  text "24" at 12799.71,5757 h60
  text "MIL" at 12984.46,5757 h60
  text "0.05mm (2MIL)" at 12428.46,5615.29 h60
  text "MINIMUM ANNULAR RING" at 11404.23,5611 h60
  text "EXTERNAL" at 13136.46,5611 h60
  text "PER" at 11604.23,5493 h60
  text "IPC-D-275 CLASS 2 LEVEL C" at 11824.23,5493 h60
  text "MIL, HOLES" at 13312.46,5380.71 h60
  text "+/-" at 12920,5380 h60
  text "+/-" at 13774,5380 h60
  text "REGISTRATION TOLERANCES:" at 11404.23,5375 h60
  text "METAL" at 12604,5375 h60
  text "5" at 13180.2,5375 h60
  text "3" at 14013.2,5375 h60
  text "MIL" at 14129.46,5375 h60
  text "+/-" at 13774,5262 h60
  text "HOLE SIZE TOLERANCE (UNLESS OTHERWISE SPECIFIED):" at 11404.23,5257 h60
  text "3" at 14013.2,5257 h60
  text "MIL" at 14129.46,5257 h60
  text "MATERIAL:" at 11329.46,5047.54 h60
  text "FR-4 High Tg" at 12315.9,4907.21 h60
  text "FR-408" at 11750.46,4898.64 h60
  text "OTHER" at 13238.46,4898.64 h60
  text "X" at 12161,4895 h60
  text "62 MIL (1.6mm) +/-10%" at 12070.56,4735.92 h60
  text "THICKNESS:" at 11404.23,4731.64 h60
  text "X" at 11942.4,4731.64 h60
  text "OTHER" at 13355.46,4731.64 h60
  text "TOLERANCE:" at 11404.23,4573.64 h60
  text "X" at 12243.53,4573.64 h60
  text "ANSI IPC-6012 TYPE 3 CLASS 2" at 12430.48,4573.64 h60
  text "OTHER +/-" at 12430.46,4417.64 h60
  text "BOW & TWIST:" at 11404.23,4260.64 h60
  text "X" at 12243.53,4260.64 h60
  text "ANSI IPC-6012 TYPE 3 CLASS 2" at 12430.48,4260.64 h60
  text "OTHER +/-" at 12430.46,4102.13 h60
  text "DRILLING:" at 11329.46,3963.64 h60
  text "REFERENCE:" at 11404.23,3846.64 h60
  text "X" at 12052.46,3846.64 h60
  text "AS SHOWN" at 12239.46,3846.64 h60
  text "X" at 12953.46,3846.64 h60
  text "NC_DRILL FILES" at 13090.46,3846.64 h60
  text "PTH MIN COPPER THICKNESS:" at 11404.23,3688.64 h60
  text "X" at 12754.46,3688.64 h60
  text "1MIL" at 12891.46,3688.64 h60
  text "OTHER" at 13388.46,3688.64 h60
  text "BOARD FINISH:" at 11329.46,3529.64 h60
  text "SILKSCREEN:" at 11484.68,3411.64 h60
  text "X" at 12433.46,3411.64 h60
  text "TOP" at 12559.46,3411.64 h60
  text "X" at 12943.46,3411.64 h60
  text "BOTTOM" at 13070.46,3411.64 h60
  text "SILKSCREEN COLOR:" at 11484.68,3244.64 h60
  text "X" at 12432.42,3244.64 h60
  text "WHITE" at 12559.46,3244.64 h60
  text "OTHER" at 13070.46,3244.64 h60
  text "X" at 12563.42,3085.44 h60
  text "GREEN" at 12690.46,3085.44 h60
  text "OTHER" at 13308.46,3085.44 h60
  text "SOLDER RESIST COLOR:" at 11484.68,3074.64 h60
  text "X" at 12563.42,2915.44 h60
  text "MATTE" at 12690.46,2915.44 h60
  text "SEMI-GLOSS" at 13308,2914.8 h60
  text "IMMERSION GOLD (ENIG)" at 12390.46,2726.92 h60
  text "ENEPIG" at 13728,2723.64 h60
  text "SURFACE FINISH:" at 11329.46,2722.64 h60
  text "X" at 12203.51,2722.64 h60
  text "IMM. TIN/SILVER OR EQUIV" at 11659,2565.64 h60
  text "OTHER" at 13090.46,2565.64 h60
  text "ARRAY/PANEL:" at 11329.46,2386.64 h60
  text "CUT AND TRIM PER M1 BOARD OUTLINE" at 12390.46,2382.35 h60
  text "N.C. ROUTE" at 12390.46,2230.64 h60
  text "X" at 13069.46,2230.64 h60
  text "V. SCORE" at 13256.46,2230.64 h60
  text "CERTIFICATION:" at 11329.46,2093.64 h60
  text "MATERIALS AND WORKMANSHIP FOR ALL PCBS" at 12054.46,2093.64 h60
  text "TO MEET OR EXCEED THE REQUIREMENTS OF:" at 12054.46,1995.64 h60
  text "X" at 11680.96,1859.13 h60
  text "ANSI IPC-A-600F CLASS ->" at 11819.96,1859.13 h60
  text "X" at 13459.02,1859.13 h60
  text "2" at 13577.96,1859.14 h60
  text "1" at 13262.96,1857.64 h60
  text "3" at 13931.96,1857.64 h60
  text "X" at 12495.02,1699.64 h60
  text "RoHS" at 12631.96,1699.64 h60
  text "OTHER" at 13276.36,1699.64 h60
  text "PER ORDER" at 13673.42,1699.64 h60
  text "ALL BOARDS MUST MEET OR EXCEED UL94-V0 REQUIREMENTS." at 11357,1534 h60
  text "PCB MUST BEAR THE UL94V-0 UL REGISTERED MATERIAL ID NUMBER" at 11357,1414 h60
  text "ADDITIONAL REQUIREMENTS:" at 11329.46,1240.64 h60
  text "MICROSECTION:" at 11404.23,1125.64 h60
  text "YES" at 12309.96,1125.64 h60
  text "REQUIRED" at 13171.46,969.49 h60
  text "BARE BOARD ELEC. TEST:" at 11404.23,966.64 h60
  text "NONE" at 12709.96,966.64 h60
  text "X" at 13044.46,966.64 h60
  text "PER ORDER" at 13763.46,966.64 h60
  text ".Layer_Name" at 577,-858.49 h60
M11 Gerber Information:
  lines w10: -292,-930.17 6308,-930.17 ; -292,-726.83 6310,-726.83 ; -292,-523.5 -292,-1133.5 3713,-1133.5 6310,-1133.5 6310,-523.5 -291.5,-523.5 -291.5,-1133.5 1284,-1133.5 ; 2173,-1133.5 2173,-523.5 ; 3440,-726.83 3440,-523.5 ; 4280,-726.83 4280,-523.5 ; 4902,-1140 4902,-937.17
  text "ALL ARTWORK VIEWED FROM TOP SIDE" at -228.5,-655.67 h60
  text "BOARD #:" at 2248,-655.67 h60
  text ".PRJ_Number" at 2793.5,-655.67 h60
  text "REV:" at 3638,-655.67 h60
  text ".PCB_Rev" at 3929.5,-655.67 h60
  text "SVN REV:" at 4476,-655.67 h60
  text ".VersionControl_RevNumber" at 4982,-655.67 h60
  text "LAYER NAME =" at -228.5,-858.49 h60
  text "TID #:" at 2248,-859 h60
  text ".TID" at 2793.5,-859 h60
  text "PLOT NAME =" at -228.5,-1064.34 h60
  text ".plot_File_Name" at 577,-1064.34 h60
  text "GENERATED    :" at 2250,-1064.34 h60
  text ".Print_Date" at 3119.5,-1064.34 h60
  text ".Print_Time" at 3848.5,-1064.34 h60
  text "TEXAS INSTRUMENTS" at 5113,-1064.34 h60
M12 Stackup:
  drawing of 295 lines, arcs and shapes, not listed
  text "Layer" at 9330,7850 h60
  text "Name" at 9739.91,7850 h60
  text "Material" at 11149.5,7850 h60
  text "Thickness" at 12009.27,7850 h60
  text "Constant" at 12659.1,7850 h60
  text "Board Layer Stack" at 13228.97,7850 h60
  text "1" at 9330,7730 h60
  text "Top Overlay" at 9739.91,7730 h60
  text "2" at 9330,7610 h60
  text "Top Solder" at 9739.91,7610 h60
  text "Solder Resist" at 11149.5,7610 h60
  text "0.40mil" at 12009.27,7610 h60
  text "3.5" at 12659.1,7610 h60
  text "3" at 9330,7490 h60
  text "Layer 1 - Top Layer" at 9739.91,7490 h60
  text "Copper" at 11149.5,7490 h60
  text "1.40mil" at 12009.27,7490 h60
  text "4" at 9330,7370 h60
  text "Dielectric 1" at 9739.91,7370 h60
  text "370HR" at 11149.5,7370 h60
  text "18.60mil" at 12009.27,7370 h60
  text "4.2" at 12659.1,7370 h60
  text "5" at 9330,7250 h60
  text "Layer 2 - GND" at 9739.91,7250 h60
  text "Copper" at 11149.5,7250 h60
  text "1.42mil" at 12009.27,7250 h60
  text "6" at 9330,7130 h60
  text "Dielectric 2" at 9739.91,7130 h60
  text "370HR" at 11149.5,7130 h60
  text "18.60mil" at 12009.27,7130 h60
  text "4.2" at 12659.1,7130 h60
  text "7" at 9330,7010 h60
  text "Layer 3 - PWR" at 9739.91,7010 h60
  text "Copper" at 11149.5,7010 h60
  text "1.42mil" at 12009.27,7010 h60
  text "8" at 9330,6890 h60
  text "Dielectric 3" at 9739.91,6890 h60
  text "370HR" at 11149.5,6890 h60
  text "18.60mil" at 12009.27,6890 h60
  text "4.2" at 12659.1,6890 h60
  text "9" at 9330,6770 h60
  text "Layer 4 - Bottom Layer" at 9739.91,6770 h60
  text "Copper" at 11149.5,6770 h60
  text "1.40mil" at 12009.27,6770 h60
  text "10" at 9330,6650 h60
  text "Bottom Solder" at 9739.91,6650 h60
  text "Solder Resist" at 11149.5,6650 h60
  text "0.40mil" at 12009.27,6650 h60
  text "3.5" at 12659.1,6650 h60
  text "11" at 9330,6530 h60
  text "Bottom Overlay" at 9739.91,6530 h60
  text ".Layer_Name" at 577,-858.49 h60
M13 Component Bodies Top:
  text ".Layer_Name" at 577,-858.49 h60
M14 Component Bodies Bottom:
  text ".Layer_Name" at 577,-858.49 h60
M15 Courtyards Top:
  text ".Layer_Name" at 577,-858.49 h60
M16 Courtyards Bottom:
  text ".Layer_Name" at 577,-858.49 h60
Drill Drawing:
  circle w10: c3668.8,1454.14 r22.1
  circle w10: c3668.8,1354.68 r13.26
  circle w10: c3668.8,1354.68 r22.1
  lines w10: 3646.69,647.49 3657.74,647.49 3668.8,636.43 3679.85,647.49 3690.9,647.49 3679.85,658.53 3690.9,669.59 3679.85,669.59 3668.8,680.64 3657.74,669.59 3646.69,669.59 3657.74,658.53 3646.69,647.49 ; 3646.69,835.34 3668.8,846.39 3690.9,835.34 3679.85,857.43 3690.9,879.53 3668.8,868.49 3646.69,879.53 3657.74,857.43 3646.69,835.34 ; 3646.69,1045.28 3657.74,1045.28 3668.8,1034.24 3679.85,1045.28 3690.9,1045.28 3679.85,1056.34 3690.9,1067.39 3679.85,1067.39 3668.8,1078.43 3657.74,1067.39 3646.69,1067.39 3657.74,1056.34 3646.69,1045.28 ; 3646.69,1133.68 3690.9,1133.68 3690.9,1177.89 3646.69,1177.89 3646.69,1133.68 ; 3646.69,1277.34 3690.9,1277.34 3668.8,1233.14 3646.69,1277.34 ; 3646.69,1531.49 3668.8,1542.53 3690.9,1531.49 3679.85,1553.59 3690.9,1575.68 3668.8,1564.64 3646.69,1575.68 3657.74,1553.59 3646.69,1531.49 ; 3646.69,1641.99 3657.74,1641.99 3657.74,1630.93 3679.85,1630.93 3679.85,1641.99 3690.9,1641.99 3690.9,1664.09 3679.85,1664.09 3679.85,1675.14 3657.74,1675.14 3657.74,1664.09 3646.69,1664.09 3646.69,1641.99 ; 3655.53,1049.7 3662.16,1049.7 3668.8,1043.07 3675.43,1049.7 3682.06,1049.7 3675.43,1056.34 3682.06,1062.97 3675.43,1062.97 3668.8,1069.59 3662.16,1062.97 3655.53,1062.97 3662.16,1056.34 3655.53,1049.7 ; 3655.53,1142.53 3682.06,1142.53 3682.06,1169.05 3655.53,1169.05 3655.53,1142.53 ; 3655.53,1540.32 3668.8,1546.95 3682.06,1540.32 3675.43,1553.59 3682.06,1566.84 3668.8,1560.22 3655.53,1566.84 3662.16,1553.59 3655.53,1540.32 ; 3655.53,1646.41 3662.16,1646.41 3662.16,1639.78 3675.43,1639.78 3675.43,1646.41 3682.06,1646.41 3682.06,1659.66 3675.43,1659.66 3675.43,1666.3 3662.16,1666.3 3662.16,1659.66 3655.53,1659.66 3655.53,1646.41
  lines w12: 3606,606.6 5495.36,606.6 ; 3606,1700.55 5495.36,1700.55 ; 3921.66,507.15 3921.66,1800 ; 4238.77,507.15 4238.77,1800 ; 4860.77,507.15 4860.77,1800 ; 5105.12,507.15 5105.12,1800 ; 3606,507.15 5495.36,507.15 5495.36,1800 3606,1800 3606,507.15
  text "Symbol" at 3665.67,1730.39 h72
  text "Quantity" at 3951.5,1730.39 h72
  text "Finished Hole Size" at 4268.6,1730.39 h72
  text "Plated" at 4890.6,1730.39 h72
  text "Hole Type" at 5134.95,1730.39 h72
  text "3" at 3951.5,1630.93 h60
  text "7.87mil (0.200mm)" at 4268.6,1630.93 h60
  text "PTH" at 4890.6,1630.93 h60
  text "Round" at 5134.95,1630.93 h60
  text "127" at 3951.5,1531.49 h60
  text "10.00mil (0.254mm)" at 4268.6,1531.49 h60
  text "PTH" at 4890.6,1531.49 h60
  text "Round" at 5134.95,1531.49 h60
  text "9" at 3951.5,1432.03 h60
  text "33.46mil (0.850mm)" at 4268.6,1432.03 h60
  text "PTH" at 4890.6,1432.03 h60
  text "Round" at 5134.95,1432.03 h60
  text "44" at 3951.5,1332.59 h60
  text "35.43mil (0.900mm)" at 4268.6,1332.59 h60
  text "PTH" at 4890.6,1332.59 h60
  text "Round" at 5134.95,1332.59 h60
  text "14" at 3951.5,1233.14 h60
  text "37.00mil (0.940mm)" at 4268.6,1233.14 h60
  text "PTH" at 4890.6,1233.14 h60
  text "Round" at 5134.95,1233.14 h60
  text "12" at 3951.5,1133.68 h60
  text "39.37mil (1.000mm)" at 4268.6,1133.68 h60
  text "PTH" at 4890.6,1133.68 h60
  text "Round" at 5134.95,1133.68 h60
  text "2" at 3951.5,1034.24 h60
  text "40.00mil (1.016mm)" at 4268.6,1034.24 h60
  text "PTH" at 4890.6,1034.24 h60
  text "Round" at 5134.95,1034.24 h60
  text "9" at 3951.5,934.78 h60
  text "43.00mil (1.092mm)" at 4268.6,934.78 h60
  text "PTH" at 4890.6,934.78 h60
  text "Round" at 5134.95,934.78 h60
  text "G" at 3644.07,924.79 h44.2
  text "6" at 3951.5,835.34 h60
  text "70.87mil (1.800mm)" at 4268.6,835.34 h60
  text "PTH" at 4890.6,835.34 h60
  text "Round" at 5134.95,835.34 h60
  text "2" at 3951.5,735.89 h60
  text "120.08mil (3.050mm)" at 4268.6,735.89 h60
  text "PTH" at 4890.6,735.89 h60
  text "Round" at 5134.95,735.89 h60
  text "A" at 3644.07,725.89 h44.2
  text "4" at 3951.5,636.43 h60
  text "125.98mil (3.200mm)" at 4268.6,636.43 h60
  text "PTH" at 4890.6,636.43 h60
  text "Round" at 5134.95,636.43 h60
  text "232 Total" at 3951.5,536.99 h60
  text ".Layer_Name" at 577,-858.49 h60
M17 Embedded Cavity:
  text ".Layer_Name" at 577,-858.49 h60
M18 Embedded Assembly:
  text ".Layer_Name" at 577,-858.49 h60
M19 Embedded Keepout:
  text ".Layer_Name" at 577,-858.49 h60

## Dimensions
0,-400 to 1000,-400 on M2 Board Dimensions
0,0 to 2700,0 on M2 Board Dimensions
0,0 to 0,5000 on M2 Board Dimensions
